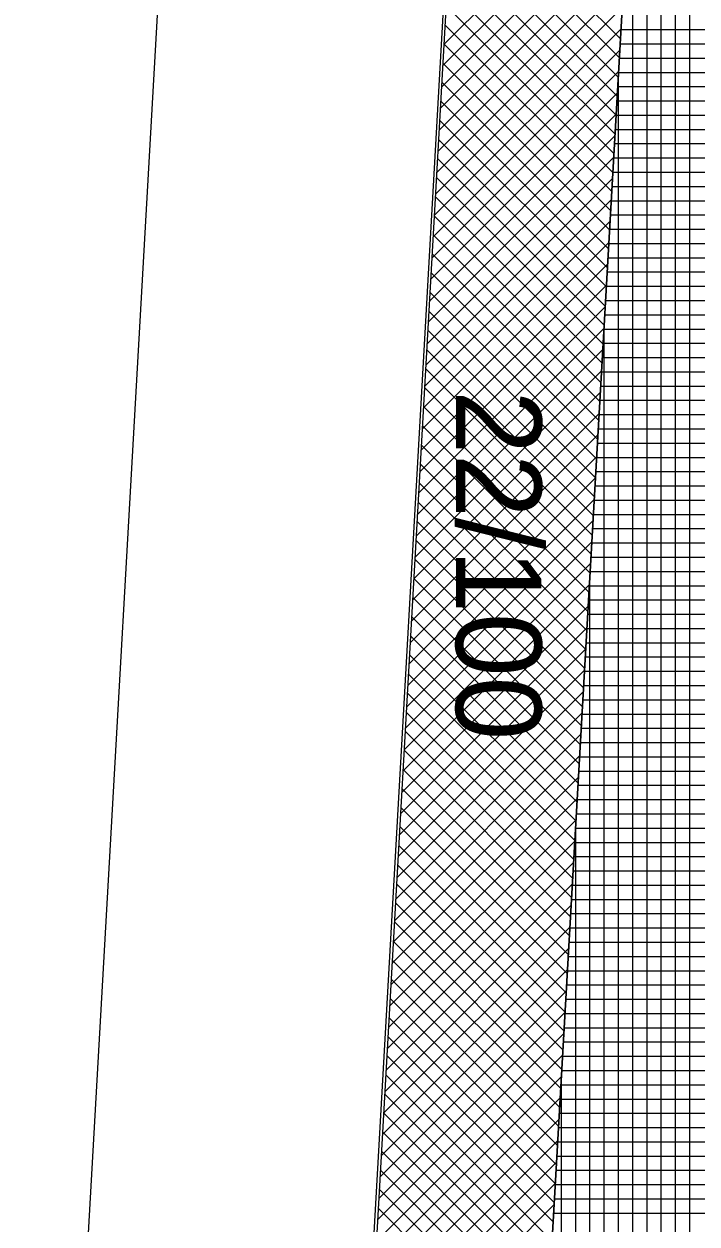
# Model space of a CAD drawing. Extents: x -565346 to -564154, y -1097386 to -1095620.
# Drawn here: x -564275.73 to -564266.29, y -1096683.14 to -1096666.31 of the extents above; entities that cross this region are included whole.
import ezdxf

# ---------------------------------------------------------------- set-up
doc = ezdxf.new("R2010")
doc.units = 0
for name, color, linetype in [('Vrstva 1', 7, 'Continuous'), ('Vrstva 40', 7, 'Continuous'), ('Vrstva 41', 7, 'Continuous'), ('Vrstva 42', 7, 'Continuous'), ('Vrstva 43', 7, 'Continuous')]:
    doc.layers.add(name, color=color, linetype=linetype)

msp = doc.modelspace()

# ---------------------------------------------------------------- linework, layer by layer
at = {"layer": 'Vrstva 1'}
for p, q in [((-564268.71, -1096575.5), (-564276.14, -1096706.4)), ((-564275.31, -1096762.41), (-564264.72, -1096575.85))]:
    msp.add_line(p, q, dxfattribs=at)
at = {"layer": 'Vrstva 41'}
msp.add_lwpolyline([(-564230.6, -1096442.93), (-564234.67, -1096447.65), (-564259.14, -1096527.84), (-564264.72, -1096575.85), (-564272.07, -1096706.16), (-564269.623, -1096706.334), (-564262.228, -1096576.061), (-564256.683, -1096528.354)], close=True, dxfattribs=at)
at = {"layer": 'Vrstva 42'}
for p, q in [((-564267.219, -1096663.98), (-564269.839, -1096666.6)), ((-564269.702, -1096664.182), (-564267.363, -1096666.521)), ((-564267.236, -1096664.28), (-564269.856, -1096666.899)), ((-564267.253, -1096664.579), (-564269.872, -1096667.199)), ((-564269.717, -1096664.449), (-564267.378, -1096666.788)), ((-564269.732, -1096664.717), (-564267.393, -1096667.056)), ((-564267.27, -1096664.879), (-564269.889, -1096667.499)), ((-564269.748, -1096664.985), (-564267.409, -1096667.324)), ((-564267.287, -1096665.179), (-564269.906, -1096667.799)), ((-564269.763, -1096665.253), (-564267.424, -1096667.591)), ((-564267.304, -1096665.479), (-564269.923, -1096668.098)), ((-564269.778, -1096665.52), (-564267.439, -1096667.859)), ((-564267.321, -1096665.779), (-564269.94, -1096668.398)), ((-564269.793, -1096665.788), (-564267.454, -1096668.127)), ((-564267.338, -1096666.079), (-564269.957, -1096668.698)), ((-564269.808, -1096666.056), (-564267.469, -1096668.394)), ((-564267.355, -1096666.379), (-564269.974, -1096668.998)), ((-564269.823, -1096666.323), (-564267.485, -1096668.662)), ((-564269.838, -1096666.591), (-564267.5, -1096668.93)), ((-564267.372, -1096666.678), (-564269.991, -1096669.297)), ((-564269.853, -1096666.859), (-564267.515, -1096669.197)), ((-564267.389, -1096666.978), (-564270.008, -1096669.597)), ((-564267.406, -1096667.278), (-564270.025, -1096669.897)), ((-564269.868, -1096667.127), (-564267.53, -1096669.465)), ((-564269.883, -1096667.394), (-564267.545, -1096669.733)), ((-564267.423, -1096667.578), (-564270.042, -1096670.197)), ((-564269.899, -1096667.662), (-564267.56, -1096670)), ((-564267.44, -1096667.878), (-564270.058, -1096670.496)), ((-564269.914, -1096667.93), (-564267.576, -1096670.268)), ((-564267.457, -1096668.178), (-564270.075, -1096670.796)), ((-564269.929, -1096668.198), (-564267.591, -1096670.536)), ((-564269.944, -1096668.465), (-564267.606, -1096670.803)), ((-564267.474, -1096668.478), (-564270.092, -1096671.096)), ((-564267.491, -1096668.778), (-564270.109, -1096671.396)), ((-564269.959, -1096668.733), (-564267.621, -1096671.071)), ((-564267.508, -1096669.077), (-564270.126, -1096671.695)), ((-564269.974, -1096669.001), (-564267.636, -1096671.338)), ((-564269.989, -1096669.269), (-564267.652, -1096671.606)), ((-564267.525, -1096669.377), (-564270.143, -1096671.995)), ((-564270.004, -1096669.536), (-564267.667, -1096671.874)), ((-564267.542, -1096669.677), (-564270.16, -1096672.295)), ((-564270.019, -1096669.804), (-564267.682, -1096672.141)), ((-564267.559, -1096669.977), (-564270.177, -1096672.595)), ((-564270.034, -1096670.072), (-564267.697, -1096672.409)), ((-564267.576, -1096670.277), (-564270.194, -1096672.894)), ((-564270.05, -1096670.34), (-564267.712, -1096672.677)), ((-564267.593, -1096670.577), (-564270.211, -1096673.194)), ((-564270.065, -1096670.607), (-564267.728, -1096672.944)), ((-564267.61, -1096670.877), (-564270.227, -1096673.494)), ((-564270.08, -1096670.875), (-564267.743, -1096673.212)), ((-564270.095, -1096671.143), (-564267.758, -1096673.48)), ((-564267.627, -1096671.176), (-564270.244, -1096673.794)), ((-564267.644, -1096671.476), (-564270.261, -1096674.093)), ((-564270.11, -1096671.411), (-564267.773, -1096673.747)), ((-564267.661, -1096671.776), (-564270.278, -1096674.393)), ((-564270.125, -1096671.678), (-564267.788, -1096674.015)), ((-564270.14, -1096671.946), (-564267.804, -1096674.283)), ((-564267.678, -1096672.076), (-564270.295, -1096674.693)), ((-564270.155, -1096672.214), (-564267.819, -1096674.55)), ((-564267.695, -1096672.376), (-564270.312, -1096674.993)), ((-564270.17, -1096672.482), (-564267.834, -1096674.818)), ((-564267.712, -1096672.676), (-564270.329, -1096675.292)), ((-564270.186, -1096672.749), (-564267.849, -1096675.086)), ((-564267.729, -1096672.976), (-564270.346, -1096675.592)), ((-564270.201, -1096673.017), (-564267.864, -1096675.353)), ((-564267.746, -1096673.275), (-564270.363, -1096675.892)), ((-564270.216, -1096673.285), (-564267.88, -1096675.621)), ((-564267.763, -1096673.575), (-564270.38, -1096676.192)), ((-564270.231, -1096673.552), (-564267.895, -1096675.889)), ((-564270.246, -1096673.82), (-564267.91, -1096676.156)), ((-564267.78, -1096673.875), (-564270.397, -1096676.491)), ((-564267.797, -1096674.175), (-564270.413, -1096676.791)), ((-564270.261, -1096674.088), (-564267.925, -1096676.424)), ((-564270.276, -1096674.356), (-564267.94, -1096676.691)), ((-564267.815, -1096674.475), (-564270.43, -1096677.091)), ((-564270.291, -1096674.623), (-564267.956, -1096676.959)), ((-564267.832, -1096674.775), (-564270.447, -1096677.391)), ((-564270.306, -1096674.891), (-564267.971, -1096677.227)), ((-564267.849, -1096675.075), (-564270.464, -1096677.69)), ((-564270.321, -1096675.159), (-564267.986, -1096677.494)), ((-564267.866, -1096675.375), (-564270.481, -1096677.99)), ((-564270.337, -1096675.427), (-564268.001, -1096677.762)), ((-564267.883, -1096675.674), (-564270.498, -1096678.29)), ((-564270.352, -1096675.694), (-564268.016, -1096678.03)), ((-564267.9, -1096675.974), (-564270.515, -1096678.59)), ((-564270.367, -1096675.962), (-564268.031, -1096678.297)), ((-564267.917, -1096676.274), (-564270.532, -1096678.889)), ((-564270.382, -1096676.23), (-564268.047, -1096678.565)), ((-564270.397, -1096676.498), (-564268.062, -1096678.833)), ((-564267.934, -1096676.574), (-564270.549, -1096679.189)), ((-564267.951, -1096676.874), (-564270.566, -1096679.489)), ((-564270.412, -1096676.765), (-564268.077, -1096679.1)), ((-564270.427, -1096677.033), (-564268.092, -1096679.368)), ((-564267.968, -1096677.174), (-564270.583, -1096679.789)), ((-564270.442, -1096677.301), (-564268.107, -1096679.636)), ((-564267.985, -1096677.474), (-564270.599, -1096680.088)), ((-564270.457, -1096677.569), (-564268.123, -1096679.903)), ((-564268.002, -1096677.773), (-564270.616, -1096680.388)), ((-564270.472, -1096677.836), (-564268.138, -1096680.171)), ((-564268.019, -1096678.073), (-564270.633, -1096680.688)), ((-564270.488, -1096678.104), (-564268.153, -1096680.439)), ((-564268.036, -1096678.373), (-564270.65, -1096680.988)), ((-564270.503, -1096678.372), (-564268.168, -1096680.706)), ((-564268.053, -1096678.673), (-564270.667, -1096681.287)), ((-564270.518, -1096678.64), (-564268.183, -1096680.974)), ((-564268.07, -1096678.973), (-564270.684, -1096681.587)), ((-564270.533, -1096678.907), (-564268.199, -1096681.242)), ((-564270.548, -1096679.175), (-564268.214, -1096681.509)), ((-564268.087, -1096679.273), (-564270.701, -1096681.887)), ((-564268.104, -1096679.573), (-564270.718, -1096682.187)), ((-564270.563, -1096679.443), (-564268.229, -1096681.777)), ((-564270.578, -1096679.711), (-564268.244, -1096682.044)), ((-564268.121, -1096679.873), (-564270.735, -1096682.486)), ((-564270.593, -1096679.978), (-564268.259, -1096682.312)), ((-564268.138, -1096680.172), (-564270.752, -1096682.786)), ((-564270.608, -1096680.246), (-564268.275, -1096682.58)), ((-564268.155, -1096680.472), (-564270.769, -1096683.086)), ((-564270.623, -1096680.514), (-564268.29, -1096682.847)), ((-564268.172, -1096680.772), (-564270.785, -1096683.386)), ((-564270.639, -1096680.781), (-564268.305, -1096683.115)), ((-564268.189, -1096681.072), (-564270.802, -1096683.685)), ((-564270.654, -1096681.049), (-564268.32, -1096683.383)), ((-564268.206, -1096681.372), (-564270.819, -1096683.985)), ((-564270.669, -1096681.317), (-564268.335, -1096683.65)), ((-564270.684, -1096681.585), (-564268.351, -1096683.918)), ((-564268.223, -1096681.672), (-564270.836, -1096684.285)), ((-564270.699, -1096681.852), (-564268.366, -1096684.186)), ((-564268.24, -1096681.972), (-564270.853, -1096684.585)), ((-564270.714, -1096682.12), (-564268.381, -1096684.453)), ((-564268.257, -1096682.271), (-564270.87, -1096684.884)), ((-564270.729, -1096682.388), (-564268.396, -1096684.721)), ((-564268.274, -1096682.571), (-564270.887, -1096685.184)), ((-564270.744, -1096682.656), (-564268.411, -1096684.989)), ((-564268.291, -1096682.871), (-564270.904, -1096685.484)), ((-564270.759, -1096682.923), (-564268.427, -1096685.256))]:
    msp.add_line(p, q, dxfattribs=at)
at = {"layer": 'Vrstva 43'}
for p, q in [((-564266.39, -1096781.673), (-564266.39, -1096649.38)), ((-564266.59, -1096785.197), (-564266.59, -1096652.904)), ((-564266.79, -1096788.72), (-564266.79, -1096656.427)), ((-564266.99, -1096792.244), (-564266.99, -1096659.95)), ((-564267.19, -1096795.767), (-564267.19, -1096663.473)), ((-564267.356, -1096666.39), (-564259.845, -1096666.39)), ((-564267.367, -1096666.59), (-564259.857, -1096666.59)), ((-564267.378, -1096666.79), (-564259.868, -1096666.79)), ((-564267.39, -1096666.99), (-564259.879, -1096666.99)), ((-564267.39, -1096799.29), (-564267.39, -1096666.997)), ((-564267.401, -1096667.19), (-564259.891, -1096667.19)), ((-564267.412, -1096667.39), (-564259.902, -1096667.39)), ((-564267.424, -1096667.59), (-564259.913, -1096667.59)), ((-564267.435, -1096667.79), (-564259.925, -1096667.79)), ((-564267.446, -1096667.99), (-564259.936, -1096667.99)), ((-564267.458, -1096668.19), (-564259.947, -1096668.19)), ((-564267.469, -1096668.39), (-564259.959, -1096668.39)), ((-564267.48, -1096668.59), (-564259.97, -1096668.59)), ((-564267.492, -1096668.79), (-564259.981, -1096668.79)), ((-564267.503, -1096668.99), (-564259.993, -1096668.99)), ((-564267.515, -1096669.19), (-564260.004, -1096669.19)), ((-564267.526, -1096669.39), (-564260.015, -1096669.39)), ((-564267.537, -1096669.59), (-564260.027, -1096669.59)), ((-564267.549, -1096669.79), (-564260.038, -1096669.79)), ((-564267.56, -1096669.99), (-564260.05, -1096669.99)), ((-564267.571, -1096670.19), (-564260.061, -1096670.19)), ((-564267.583, -1096670.39), (-564260.072, -1096670.39)), ((-564267.594, -1096670.59), (-564260.084, -1096670.59)), ((-564267.59, -1096802.814), (-564267.59, -1096670.52)), ((-564267.605, -1096670.79), (-564260.095, -1096670.79)), ((-564267.617, -1096670.99), (-564260.106, -1096670.99)), ((-564267.628, -1096671.19), (-564260.118, -1096671.19)), ((-564267.639, -1096671.39), (-564260.129, -1096671.39)), ((-564267.651, -1096671.59), (-564260.14, -1096671.59)), ((-564267.662, -1096671.79), (-564260.152, -1096671.79)), ((-564267.673, -1096671.99), (-564260.163, -1096671.99)), ((-564267.685, -1096672.19), (-564260.174, -1096672.19)), ((-564267.696, -1096672.39), (-564260.186, -1096672.39)), ((-564267.708, -1096672.59), (-564260.197, -1096672.59)), ((-564267.719, -1096672.79), (-564260.209, -1096672.79)), ((-564267.73, -1096672.99), (-564260.22, -1096672.99)), ((-564267.742, -1096673.19), (-564260.231, -1096673.19)), ((-564267.753, -1096673.39), (-564260.243, -1096673.39)), ((-564267.764, -1096673.59), (-564260.254, -1096673.59)), ((-564267.776, -1096673.79), (-564260.265, -1096673.79)), ((-564267.787, -1096673.99), (-564260.277, -1096673.99)), ((-564267.79, -1096806.337), (-564267.79, -1096674.043)), ((-564267.798, -1096674.19), (-564260.288, -1096674.19)), ((-564267.81, -1096674.39), (-564260.299, -1096674.39)), ((-564267.821, -1096674.59), (-564260.311, -1096674.59)), ((-564267.832, -1096674.79), (-564260.322, -1096674.79)), ((-564267.844, -1096674.99), (-564260.333, -1096674.99)), ((-564267.855, -1096675.19), (-564260.345, -1096675.19)), ((-564267.866, -1096675.39), (-564260.356, -1096675.39)), ((-564267.878, -1096675.59), (-564260.367, -1096675.59)), ((-564267.889, -1096675.79), (-564260.379, -1096675.79)), ((-564267.901, -1096675.99), (-564260.39, -1096675.99)), ((-564267.912, -1096676.19), (-564260.402, -1096676.19)), ((-564267.923, -1096676.39), (-564260.413, -1096676.39)), ((-564267.935, -1096676.59), (-564260.424, -1096676.59)), ((-564267.946, -1096676.79), (-564260.436, -1096676.79)), ((-564267.957, -1096676.99), (-564260.447, -1096676.99)), ((-564267.969, -1096677.19), (-564260.458, -1096677.19)), ((-564267.98, -1096677.39), (-564260.47, -1096677.39)), ((-564267.991, -1096677.59), (-564260.481, -1096677.59)), ((-564267.99, -1096809.861), (-564267.99, -1096677.566)), ((-564268.003, -1096677.79), (-564260.492, -1096677.79)), ((-564268.014, -1096677.99), (-564260.504, -1096677.99)), ((-564268.025, -1096678.19), (-564260.515, -1096678.19)), ((-564268.037, -1096678.39), (-564260.526, -1096678.39)), ((-564268.048, -1096678.59), (-564260.538, -1096678.59)), ((-564268.059, -1096678.79), (-564260.549, -1096678.79)), ((-564268.071, -1096678.99), (-564260.561, -1096678.99)), ((-564268.082, -1096679.19), (-564260.572, -1096679.19)), ((-564268.094, -1096679.39), (-564260.583, -1096679.39)), ((-564268.105, -1096679.59), (-564260.595, -1096679.59)), ((-564268.116, -1096679.79), (-564260.606, -1096679.79)), ((-564268.128, -1096679.99), (-564260.617, -1096679.99)), ((-564268.139, -1096680.19), (-564260.629, -1096680.19)), ((-564268.15, -1096680.39), (-564260.64, -1096680.39)), ((-564268.162, -1096680.59), (-564260.651, -1096680.59)), ((-564268.173, -1096680.79), (-564260.663, -1096680.79)), ((-564268.19, -1096813.384), (-564268.19, -1096681.09)), ((-564268.184, -1096680.99), (-564260.674, -1096680.99)), ((-564268.196, -1096681.19), (-564260.685, -1096681.19)), ((-564268.207, -1096681.39), (-564260.697, -1096681.39)), ((-564268.218, -1096681.59), (-564260.708, -1096681.59)), ((-564268.23, -1096681.79), (-564260.719, -1096681.79)), ((-564268.241, -1096681.99), (-564260.731, -1096681.99)), ((-564268.252, -1096682.19), (-564260.742, -1096682.19)), ((-564268.264, -1096682.39), (-564260.754, -1096682.39)), ((-564268.275, -1096682.59), (-564260.765, -1096682.59)), ((-564268.287, -1096682.79), (-564260.776, -1096682.79)), ((-564268.298, -1096682.99), (-564260.788, -1096682.99))]:
    msp.add_line(p, q, dxfattribs=at)
msp.add_lwpolyline([(-564261.274, -1096726.84), (-564260.141, -1096706.872), (-564262.137, -1096706.758), (-564254.757, -1096576.767), (-564249.271, -1096529.938), (-564240.675, -1096505.018), (-564228.215, -1096460.758), (-564223.301, -1096445.676), (-564221.399, -1096446.296), (-564218.92, -1096438.69), (-564229.82, -1096442.05), (-564230.6, -1096442.93), (-564256.683, -1096528.354), (-564262.228, -1096576.061), (-564269.623, -1096706.334), (-564272.07, -1096706.16), (-564273.28, -1096725.96)], dxfattribs=at)

# ---------------------------------------------------------------- texts
at = {"layer": 'Vrstva 40'}
msp.add_text('22/100', height=1.2, rotation=270, dxfattribs=at).set_placement((-564269.67, -1096671.45))

doc.saveas('drawing.dxf')
